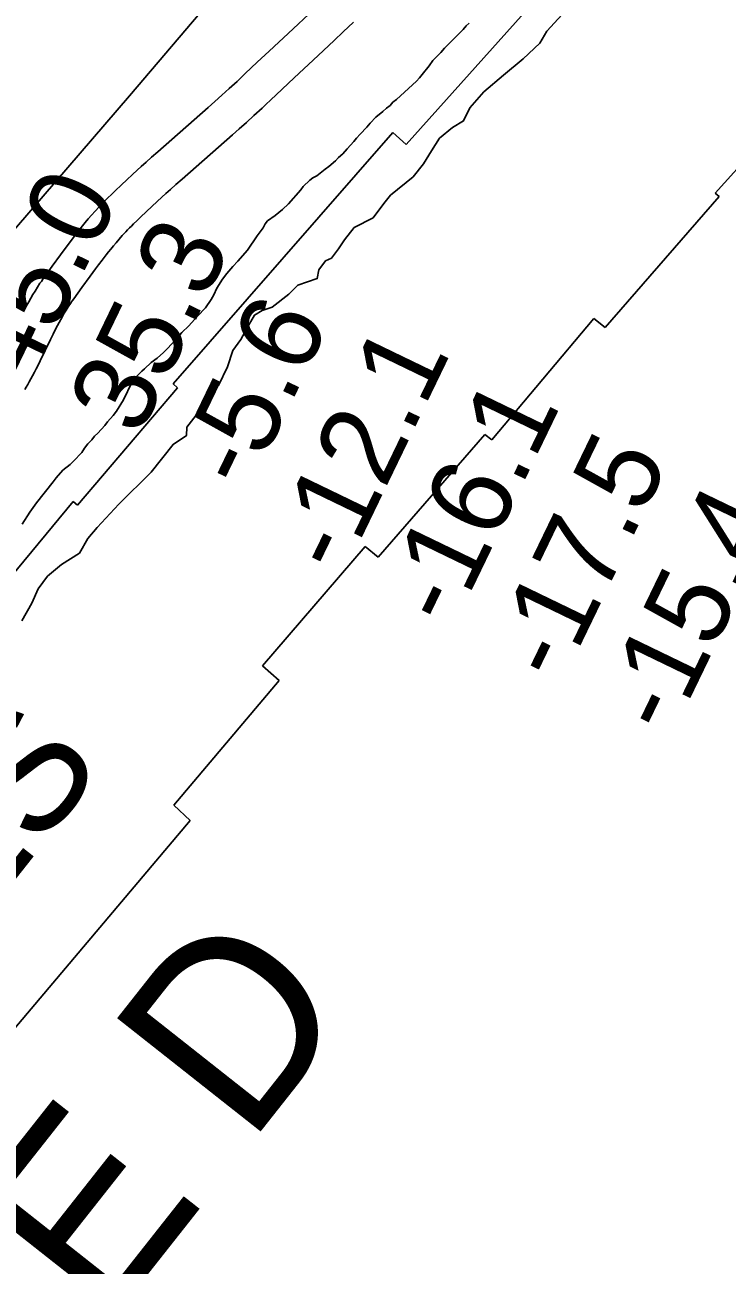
# Model space of a CAD drawing. Extents: x 3146026 to 3183936, y 897894 to 923344.
# Drawn here: x 3150766 to 3151343, y 917753 to 918770 of the extents above; entities that cross this region are included whole.
import ezdxf

# ---------------------------------------------------------------- set-up
doc = ezdxf.new("R2010")
doc.units = 0
for name, color, linetype in [('V-RIVR-EDGE', 7, 'Continuous'), ('V-RIVR-IDEN', 7, 'Continuous'), ('V-RIVR-RANG', 7, 'Continuous'), ('V-ROAD-CNTR', 7, 'Continuous'), ('V-RRAP-RVMT', 7, 'Continuous'), ('V-RRAP-RVMT-IDEN', 7, 'Continuous'), ('V-SITE-VEGE', 7, 'Continuous'), ('V-WETL-SWMP', 7, 'Continuous')]:
    doc.layers.add(name, color=color, linetype=linetype)

msp = doc.modelspace()

# ---------------------------------------------------------------- linework, layer by layer
at = {"layer": 'V-RIVR-EDGE'}
msp.add_lwpolyline([(3151213.1, 918785.2), (3151194.6, 918764.9), (3151188.9, 918754.9), (3151175.2, 918742.1), (3151159.2, 918728.7), (3151142.9, 918715), (3151131.6, 918701.9), (3151126.3, 918691.3), (3151117.2, 918685.7), (3151106.6, 918677), (3151100, 918666.7), (3151093.4, 918656.1), (3151084.9, 918645.4), (3151066.4, 918630.2), (3151060.8, 918623.6), (3151052.3, 918611.8), (3151036.7, 918603.7), (3151028.8, 918593.7), (3151023.8, 918586.2), (3151017.9, 918578.7), (3151013.2, 918576.5), (3151007.5, 918569.1), (3151006.3, 918561.9), (3150990.3, 918556.6), (3150983.1, 918549.1), (3150969.3, 918538.5), (3150961.2, 918535.7), (3150954.9, 918532), (3150949.9, 918523.3), (3150943.6, 918512), (3150937, 918503), (3150932.6, 918489.5), (3150925.4, 918474.2), (3150916.3, 918464), (3150908.8, 918452.4), (3150899.4, 918439.9), (3150899, 918433.1), (3150888.1, 918425.9), (3150870.2, 918403.1), (3150843.6, 918376.9), (3150825.7, 918357.6), (3150818.2, 918348.6), (3150811.3, 918336.7), (3150796.6, 918327.4), (3150785, 918317.7), (3150777.5, 918307.4), (3150772.1, 918295.5), (3150764, 918281.2)], dxfattribs=at)
at = {"layer": 'V-ROAD-CNTR'}
for points in [[(3150999.5, 918778.9), (3150986.5, 918766.8), (3150966.9, 918748.5), (3150957.1, 918739.3), (3150947.3, 918730.1), (3150943.9, 918726.8), (3150940.6, 918723.7), (3150934.1, 918717.8), (3150928, 918712.3), (3150922.3, 918707.1), (3150916.9, 918702.3), (3150875.6, 918666), (3150870.4, 918661.4), (3150865.9, 918657.4), (3150861.9, 918653.8), (3150855, 918647.5), (3150849.9, 918642.7), (3150846, 918639.1), (3150840.3, 918633.6), (3150837.4, 918630.9), (3150834.5, 918628.1), (3150832.6, 918626.2), (3150830.8, 918624.3), (3150829, 918622.5), (3150827.3, 918620.7), (3150824.1, 918617.2), (3150821.2, 918613.9), (3150818.5, 918610.8), (3150816, 918607.9), (3150813.7, 918605.1), (3150811.6, 918602.5), (3150809.7, 918600), (3150806.1, 918595.4), (3150803, 918591.3), (3150800.3, 918587.7), (3150795.7, 918581.5), (3150788.9, 918572.2), (3150782.2, 918562.9), (3150781.1, 918561.3), (3150780, 918559.6), (3150778.8, 918558), (3150776.8, 918554.8), (3150774.8, 918551.7), (3150773, 918548.7), (3150771.3, 918545.7), (3150769.7, 918542.8), (3150768.2, 918540), (3150766.7, 918537.3), (3150765.3, 918534.7)], [(3151036, 918772.3), (3151027.5, 918764.2), (3151020.1, 918757.1), (3151007, 918744.8), (3150987.4, 918726.6), (3150977.6, 918717.4), (3150967.9, 918708.3), (3150964.4, 918705), (3150961, 918701.8), (3150954.4, 918695.7), (3150948.2, 918690), (3150942.3, 918684.7), (3150936.7, 918679.8), (3150895.4, 918643.5), (3150890.3, 918639), (3150885.9, 918635), (3150882, 918631.6), (3150875.3, 918625.4), (3150870.3, 918620.8), (3150866.6, 918617.3), (3150861, 918612), (3150858.3, 918609.4), (3150855.6, 918606.7), (3150853.9, 918605), (3150852.3, 918603.4), (3150850.7, 918601.8), (3150849.3, 918600.2), (3150846.4, 918597.1), (3150843.8, 918594.2), (3150841.3, 918591.3), (3150839.1, 918588.7), (3150837, 918586.1), (3150835, 918583.7), (3150833.2, 918581.4), (3150829.8, 918577.1), (3150826.9, 918573.2), (3150824.4, 918569.8), (3150819.9, 918563.8), (3150813.3, 918554.6), (3150806.6, 918545.4), (3150805.6, 918544), (3150804.7, 918542.7), (3150803.8, 918541.4), (3150802, 918538.7), (3150800.4, 918536), (3150798.8, 918533.4), (3150797.4, 918530.9), (3150795.9, 918528.3), (3150794.6, 918525.8), (3150793.3, 918523.4), (3150792, 918521), (3150789.6, 918516.3), (3150787.4, 918511.8), (3150779, 918494.4), (3150777.3, 918491), (3150775.8, 918487.9), (3150774.3, 918485), (3150772.8, 918482.2), (3150771.4, 918479.6), (3150770.1, 918477.2), (3150768.8, 918475), (3150767.6, 918472.9), (3150766.5, 918471)]]:
    msp.add_lwpolyline(points, dxfattribs=at)
at = {"layer": 'V-RRAP-RVMT'}
for p, q in [((3151079.3, 918671.8), (3151254.1, 918867.3)), ((3151419.5, 918728.5), (3151332.7, 918631.9)), ((3150888.1, 918475.5), (3151068.4, 918681.7)), ((3151068.4, 918681.7), (3151079.3, 918671.8)), ((3151332.7, 918631.9), (3151335.9, 918629.2)), ((3151335.9, 918629.2), (3151242.4, 918521.7)), ((3151233.2, 918529.2), (3151149.5, 918429.6)), ((3151242.4, 918521.7), (3151233.2, 918529.2)), ((3150809.7, 918376), (3150891.8, 918472.3)), ((3150891.8, 918472.3), (3150888.1, 918475.5)), ((3151143.9, 918434), (3151056.2, 918333.3)), ((3151149.5, 918429.6), (3151143.9, 918434)), ((3150718.4, 918273.3), (3150806.2, 918378.9)), ((3150806.2, 918378.9), (3150809.7, 918376)), ((3151045.5, 918342.2), (3150961.4, 918244.2)), ((3151056.2, 918333.3), (3151045.5, 918342.2)), ((3150961.4, 918244.2), (3150975.2, 918232.2)), ((3150975.2, 918232.2), (3150888.7, 918129.8)), ((3150888.7, 918129.8), (3150902, 918117.4)), ((3150902, 918117.4), (3150729.4, 917912.9))]:
    msp.add_line(p, q, dxfattribs=at)
at = {"layer": 'V-SITE-VEGE'}
for p, q in [((3151110.7, 918750.8), (3151126, 918766.2)), ((3151126, 918766.2), (3151128.4, 918769.1)), ((3151128.4, 918769.1), (3151130.8, 918771.3)), ((3151101.2, 918740.8), (3151104.9, 918744.7)), ((3151104.9, 918744.7), (3151107.8, 918747.4)), ((3151107.8, 918747.4), (3151110.7, 918750.8)), ((3151092.5, 918729.4), (3151098.1, 918736.4)), ((3151098.1, 918736.4), (3151101.2, 918740.8)), ((3151071.4, 918708.9), (3151087.6, 918723.8)), ((3151087.6, 918723.8), (3151090.3, 918726.7)), ((3151090.3, 918726.7), (3151092.5, 918729.4)), ((3151063.1, 918701.8), (3151066.1, 918704)), ((3151066.1, 918704), (3151068.2, 918706.5)), ((3151068.2, 918706.5), (3151071.4, 918708.9)), ((3151049.6, 918689.4), (3151054.4, 918694.3)), ((3151054.4, 918694.3), (3151060, 918698.9)), ((3151060, 918698.9), (3151063.1, 918701.8)), ((3151041.5, 918680.4), (3151046.9, 918686.2)), ((3151046.9, 918686.2), (3151049.6, 918689.4)), ((3151030.9, 918668.4), (3151036.2, 918674.3)), ((3151036.2, 918674.3), (3151038.4, 918677.2)), ((3151038.4, 918677.2), (3151041.5, 918680.4)), ((3151023.8, 918661.1), (3151027.2, 918664.1)), ((3151027.2, 918664.1), (3151030.9, 918668.4)), ((3151005.9, 918646.3), (3151012.7, 918651.6)), ((3151012.7, 918651.6), (3151015.8, 918653.8)), ((3151015.8, 918653.8), (3151021.4, 918658.5)), ((3151021.4, 918658.5), (3151023.8, 918661.1)), ((3150994.7, 918637.5), (3151000.1, 918642.6)), ((3151000.1, 918642.6), (3151002.7, 918644.5)), ((3151002.7, 918644.5), (3151005.9, 918646.3)), ((3150982.6, 918623.3), (3150992.8, 918634.6)), ((3150992.8, 918634.6), (3150994.7, 918637.5)), ((3150977.7, 918618.7), (3150982.6, 918623.3)), ((3150965.4, 918609.4), (3150971.9, 918613.6)), ((3150971.9, 918613.6), (3150977.7, 918618.7)), ((3150956.9, 918597), (3150962, 918603.6)), ((3150962, 918603.6), (3150963.7, 918606.8)), ((3150963.7, 918606.8), (3150965.4, 918609.4)), ((3150949.1, 918585.3), (3150956.9, 918597)), ((3150941.1, 918576.1), (3150949.1, 918585.3)), ((3150932.1, 918566.1), (3150937.2, 918571.9)), ((3150937.2, 918571.9), (3150941.1, 918576.1)), ((3150923.9, 918553.9), (3150928.7, 918561.5)), ((3150928.7, 918561.5), (3150932.1, 918566.1)), ((3150921.5, 918548.6), (3150923.9, 918553.9)), ((3150914.7, 918537.8), (3150919.3, 918544.7)), ((3150919.3, 918544.7), (3150921.5, 918548.6)), ((3150901.1, 918523.2), (3150908.2, 918531)), ((3150908.2, 918531), (3150914.7, 918537.8)), ((3150895.3, 918517.6), (3150901.1, 918523.2)), ((3150883.4, 918504.5), (3150890.2, 918511.8)), ((3150890.2, 918511.8), (3150895.3, 918517.6)), ((3150874.9, 918496.7), (3150880.3, 918501.3)), ((3150880.3, 918501.3), (3150883.4, 918504.5)), ((3150864.7, 918487.9), (3150870.1, 918493)), ((3150870.1, 918493), (3150874.9, 918496.7)), ((3150854.3, 918476.7), (3150856.2, 918479.6)), ((3150856.2, 918479.6), (3150862.3, 918485.9)), ((3150862.3, 918485.9), (3150864.7, 918487.9)), ((3150847.5, 918462.5), (3150854.3, 918476.7)), ((3150841.7, 918453.1), (3150847.5, 918462.5)), ((3150834.2, 918444.3), (3150839, 918449.6)), ((3150839, 918449.6), (3150841.7, 918453.1)), ((3150826.2, 918435), (3150832, 918441.4)), ((3150832, 918441.4), (3150834.2, 918444.3)), ((3150818.2, 918426.2), (3150821.3, 918429.7)), ((3150821.3, 918429.7), (3150823.5, 918432.6)), ((3150823.5, 918432.6), (3150826.2, 918435)), ((3150806.5, 918412.1), (3150813.1, 918419.2)), ((3150813.1, 918419.2), (3150815.5, 918422.8)), ((3150815.5, 918422.8), (3150818.2, 918426.2)), ((3150797.6, 918404.6), (3150803.6, 918409.4)), ((3150803.6, 918409.4), (3150806.5, 918412.1)), ((3150789.8, 918395.1), (3150792.2, 918398.5)), ((3150792.2, 918398.5), (3150797.6, 918404.6)), ((3150776, 918378), (3150789.8, 918395.1)), ((3150770.6, 918370.2), (3150776, 918378)), ((3150764.3, 918360.5), (3150770.6, 918370.2))]:
    msp.add_line(p, q, dxfattribs=at)
at = {"layer": 'V-WETL-SWMP'}
msp.add_lwpolyline([(3154156.3, 921550.8), (3150311.9, 921563.1), (3150299.2, 918069.2), (3150852.3, 918711.7), (3151740.5, 919755.3), (3152243.5, 920278.8), (3152339.1, 920369.4), (3152421.5, 920426.9), (3152514.9, 920450.7), (3152616.2, 920465.1), (3152932.2, 920578.6), (3153209.3, 920814.1), (3153778.6, 921266.6), (3154156.3, 921550.8)], dxfattribs=at)

# ---------------------------------------------------------------- texts
at = {"layer": 'V-RIVR-IDEN'}
msp.add_text('R E D', height=150, rotation=51.7162, dxfattribs=at).set_placement((3150708, 917543.1))
at = {"layer": 'V-RIVR-RANG'}
for s, p in [('45.0', (3150768.7, 918471.6)), ('35.3', (3150860.1, 918431)), ('-5.6', (3150949.5, 918386)), ('-12.1', (3151027, 918316.7)), ('-16.1', (3151117.1, 918273.4)), ('-17.5', (3151206.3, 918228)), ('-15.4', (3151296.4, 918184.7))]:
    msp.add_text(s, height=67, rotation=64.2183, dxfattribs=at).set_placement(p)
at = {"layer": 'V-RRAP-RVMT-IDEN'}
msp.add_text('NAPLES', height=100, rotation=51.7005, dxfattribs=at).set_placement((3150505.5, 917748.3))

doc.saveas('drawing.dxf')
